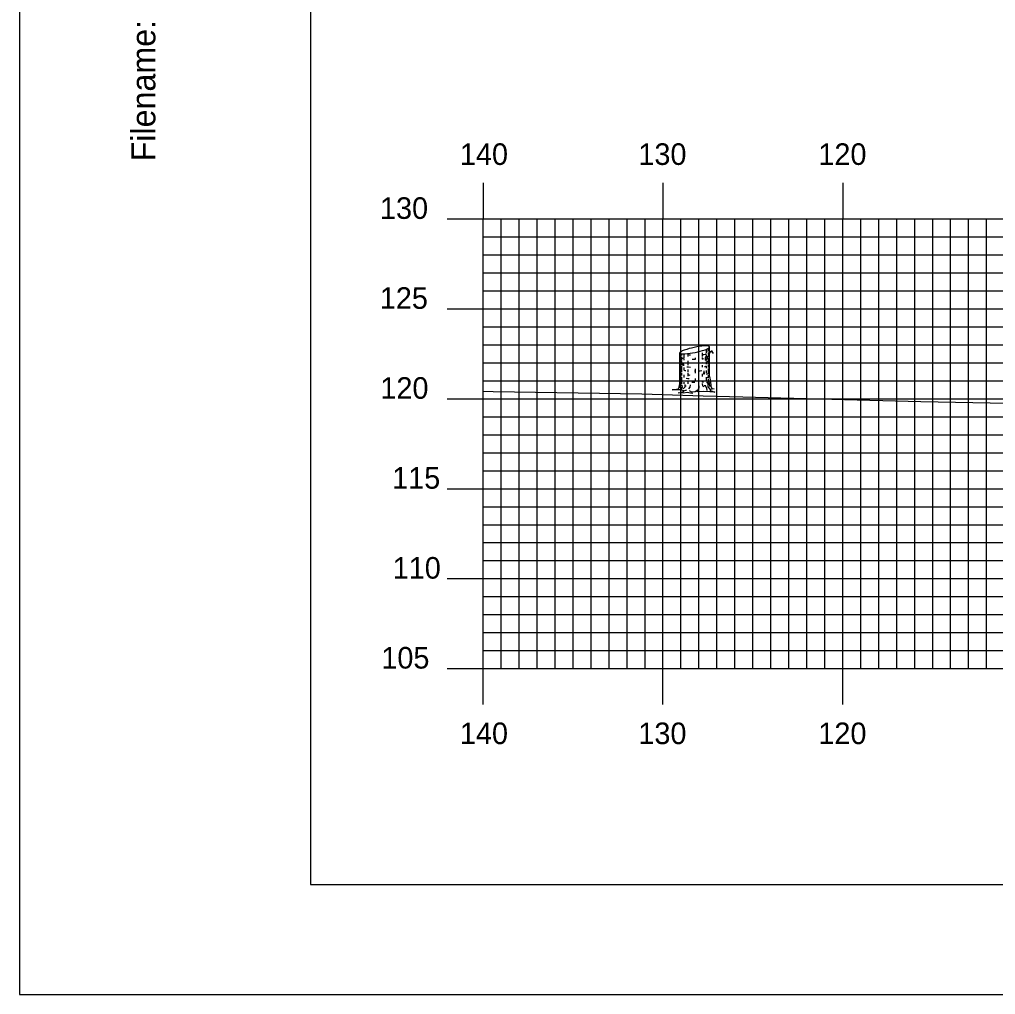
# Model space of a CAD drawing. Extents: x 1772022 to 1772366, y 442591 to 442811.
# Drawn here: x 1772022.3 to 1772076.6, y 442590.5 to 442644.7 of the extents above; entities that cross this region are included whole.
import ezdxf

# ---------------------------------------------------------------- set-up
doc = ezdxf.new("R2010")
doc.units = 0
for name, color, linetype in [('BORDER', 7, 'Continuous'), ('H_V ANNOTATION', 7, 'Continuous'), ('M_Trees_Conifer_Pay', 7, 'Continuous'), ('MAJOR', 7, 'Continuous'), ('MINOR', 7, 'Continuous'), ('PLOT BOUNDARY', 7, 'Continuous'), ('S_Roadway_Centerline', 7, 'Continuous')]:
    doc.layers.add(name, color=color, linetype=linetype)

msp = doc.modelspace()

# ---------------------------------------------------------------- linework, layer by layer
at = {"layer": 'BORDER'}
msp.add_lwpolyline([(1772038.494, 442596.665), (1772358.494, 442596.665), (1772358.494, 442806.665), (1772038.494, 442806.665)], close=True, dxfattribs=at)
at = {"layer": 'M_Trees_Conifer_Pay'}
for p, q in [((1772059.024, 442624.49), (1772059.024, 442626.212)), ((1772059.071, 442626.175), (1772059.071, 442625.704)), ((1772059.129, 442626.164), (1772059.129, 442626.066)), ((1772059.255, 442626.156), (1772059.255, 442625.923)), ((1772059.475, 442626.176), (1772059.475, 442626.008)), ((1772060.27, 442626.218), (1772060.27, 442626.019)), ((1772060.499, 442626.414), (1772060.499, 442626.191)), ((1772060.616, 442626.475), (1772060.616, 442626.313)), ((1772060.616, 442626.245), (1772060.616, 442626.117)), ((1772060.688, 442624.9), (1772060.688, 442626.547)), ((1772059.071, 442625.639), (1772059.071, 442625.331)), ((1772059.129, 442625.992), (1772059.129, 442625.788)), ((1772059.129, 442625.73), (1772059.129, 442625.53)), ((1772059.255, 442625.883), (1772059.255, 442625.809)), ((1772059.475, 442625.771), (1772059.475, 442625.534)), ((1772059.88, 442625.944), (1772059.88, 442625.849)), ((1772060.27, 442625.961), (1772060.27, 442625.872)), ((1772060.499, 442626.103), (1772060.499, 442626.055)), ((1772060.499, 442625.72), (1772060.499, 442625.588)), ((1772060.556, 442625.919), (1772060.505, 442625.86)), ((1772060.616, 442625.93), (1772060.616, 442625.594)), ((1772059.071, 442625.284), (1772059.071, 442624.792)), ((1772059.129, 442625.483), (1772059.129, 442625.147)), ((1772059.129, 442625.094), (1772059.129, 442624.958)), ((1772059.255, 442625.405), (1772059.255, 442625.267)), ((1772059.475, 442625.29), (1772059.475, 442625.137)), ((1772059.475, 442625.094), (1772059.475, 442624.921)), ((1772059.88, 442625.331), (1772059.88, 442625.257)), ((1772059.88, 442625.232), (1772059.88, 442625.084)), ((1772060.27, 442625.524), (1772060.27, 442625.419)), ((1772060.27, 442625.053), (1772060.27, 442624.906)), ((1772060.499, 442625.477), (1772060.499, 442625.368)), ((1772060.499, 442625.232), (1772060.499, 442625.09)), ((1772060.616, 442625.557), (1772060.616, 442625.395)), ((1772060.616, 442625.347), (1772060.616, 442625.131)), ((1772060.616, 442625.1), (1772060.616, 442625.026)), ((1772059.071, 442624.738), (1772059.071, 442624.49)), ((1772059.129, 442624.859), (1772059.129, 442624.481)), ((1772059.255, 442624.995), (1772059.255, 442624.853)), ((1772059.255, 442624.591), (1772059.255, 442624.497)), ((1772059.475, 442624.643), (1772059.475, 442624.49)), ((1772059.88, 442624.792), (1772059.88, 442624.639)), ((1772060.27, 442624.674), (1772060.27, 442624.586)), ((1772060.499, 442624.863), (1772060.499, 442624.69)), ((1772060.616, 442624.985), (1772060.616, 442624.812)), ((1772059.255, 442624.097), (1772059.417, 442624.161)), ((1772059.692, 442624.033), (1772059.566, 442624.097))]:
    msp.add_line(p, q, dxfattribs=at)
for points in [[(1772060.505, 442626.045), (1772060.541, 442625.971), (1772060.589, 442626.028), (1772060.646, 442626.097), (1772060.739, 442626.29), (1772060.803, 442626.337), (1772060.834, 442626.344)], [(1772060.519, 442625.792), (1772060.556, 442625.919), (1772060.62, 442626.035), (1772060.65, 442626.103), (1772060.719, 442626.249)], [(1772060.734, 442626.278), (1772060.809, 442626.286), (1772060.881, 442626.187)], [(1772059.203, 442625.518), (1772059.197, 442625.613), (1772059.24, 442625.59), (1772059.24, 442625.496)], [(1772060.471, 442626.008), (1772060.44, 442625.923), (1772060.436, 442625.856), (1772060.467, 442625.792)], [(1772060.342, 442625.119), (1772060.354, 442625.042), (1772060.402, 442625.053), (1772060.389, 442625.219)], [(1772060.688, 442624.9), (1772060.739, 442624.639), (1772060.755, 442624.365), (1772060.813, 442624.24), (1772060.949, 442624.209), (1772060.719, 442624.171), (1772060.719, 442624.171), (1772060.725, 442624.124), (1772060.972, 442624.03), (1772060.698, 442624.046), (1772060.342, 442624.066), (1772060.02, 442624.056), (1772060.027, 442624.139), (1772059.879, 442624.056), (1772059.692, 442624.033), (1772059.716, 442623.965), (1772059.448, 442624.009), (1772059.228, 442623.982), (1772058.935, 442623.999), (1772059.224, 442624.056), (1772059.255, 442624.097), (1772059.092, 442624.155), (1772058.855, 442624.166), (1772058.614, 442624.166), (1772058.956, 442624.223), (1772058.997, 442624.303), (1772059.024, 442624.49)], [(1772060.278, 442624.507), (1772060.288, 442624.381), (1772060.362, 442624.338)], [(1772060.515, 442624.612), (1772060.589, 442624.507), (1772060.593, 442624.334), (1772060.719, 442624.171)], [(1772060.614, 442624.758), (1772060.62, 442624.612), (1772060.667, 442624.544), (1772060.677, 442624.345)], [(1772059.072, 442624.443), (1772059.051, 442624.365), (1772059.03, 442624.271)], [(1772059.15, 442624.423), (1772059.156, 442624.307), (1772059.102, 442624.219), (1772059.092, 442624.155)], [(1772059.312, 442624.45), (1772059.312, 442624.318), (1772059.224, 442624.219)], [(1772059.539, 442624.209), (1772059.606, 442624.303), (1772059.633, 442624.443)], [(1772060.027, 442624.139), (1772060.101, 442624.28), (1772060.111, 442624.381)], [(1772060.556, 442624.118), (1772060.541, 442624.256), (1772060.467, 442624.385)]]:
    msp.add_lwpolyline(points, dxfattribs=at)
for centre, radius, start, end in [((1772059.055, 442626.211), 0.0314, 156.5158, 169.2194), ((1772059.05, 442626.212), 0.0264, 169.2194, 180.0315), ((1772059.046, 442626.212), 0.0226, 180.0315, 191.7194), ((1772059.046, 442626.212), 0.0226, 191.7194, 203.4074), ((1772059.075, 442626.202), 0.0527, 146.7194, 156.5158), ((1772059.05, 442626.213), 0.0264, 203.4074, 214.2194), ((1772059.054, 442626.216), 0.0314, 214.2194, 226.923), ((1772059.099, 442626.187), 0.0817, 132.3887, 146.7194), ((1772059.069, 442626.232), 0.0527, 226.923, 236.7194), ((1772059.085, 442626.256), 0.0817, 236.7194, 251.0501), ((1772059.213, 442626.062), 0.251, 124.2194, 132.3887), ((1772059.139, 442626.416), 0.251, 251.0501, 259.2194), ((1772059.523, 442625.606), 0.802, 108.0594, 124.2194), ((1772059.242, 442626.957), 0.802, 259.2194, 275.3794), ((1772060.88, 442621.445), 5.179, 101.7194, 108.0594), ((1772058.832, 442631.315), 5.179, 275.3794, 281.7194), ((1772060.88, 442621.445), 5.179, 95.3794, 101.7194), ((1772058.832, 442631.315), 5.179, 281.7194, 288.0594), ((1772059.856, 442630.224), 4.124, 276.238, 278.1032), ((1772060.469, 442625.803), 0.802, 79.2194, 95.3794), ((1772060.357, 442626.707), 0.571, 278.1032, 284.3667), ((1772060.189, 442627.153), 0.802, 288.0594, 304.2194), ((1772060.357, 442626.861), 0.571, 284.4317, 292.4132), ((1772060.357, 442626.707), 0.571, 297.0237, 300), ((1772060.572, 442626.344), 0.251, 71.0501, 79.2194), ((1772060.499, 442626.698), 0.251, 304.2194, 312.3887), ((1772060.556, 442626.516), 0.172, 300, 311.2506), ((1772060.556, 442626.361), 0.172, 300, 311.2506), ((1772060.627, 442626.504), 0.0817, 56.7194, 71.0501), ((1772060.613, 442626.573), 0.0817, 312.3887, 326.7194), ((1772060.628, 442626.433), 0.0624, 311.2506, 330), ((1772060.628, 442626.279), 0.0624, 311.2506, 330), ((1772060.643, 442626.528), 0.0527, 46.923, 56.7194), ((1772060.658, 442626.543), 0.0314, 34.2194, 46.923), ((1772060.637, 442626.557), 0.0527, 326.7194, 336.5158), ((1772060.644, 442626.424), 0.0441, 330, 343.9485), ((1772060.644, 442626.27), 0.0441, 330, 343.9485), ((1772060.662, 442626.546), 0.0264, 23.4074, 34.2194), ((1772060.657, 442626.549), 0.0314, 336.5158, 349.2194), ((1772060.665, 442626.548), 0.0226, 11.7194, 23.4074), ((1772060.665, 442626.548), 0.0226, 0.0315, 11.7194), ((1772060.661, 442626.548), 0.0264, 349.2194, 0.0315), ((1772060.655, 442626.421), 0.0334, 343.9485, 354.2151), ((1772060.655, 442626.267), 0.0334, 343.9485, 354.2151), ((1772059.056, 442626.034), 0.0334, 163.9485, 180), ((1772059.056, 442626.034), 0.0334, 180, 196.0515), ((1772059.056, 442625.587), 0.0334, 163.9485, 180), ((1772059.056, 442625.587), 0.0334, 180, 196.0515), ((1772059.066, 442626.037), 0.0441, 196.0515, 210), ((1772059.066, 442625.59), 0.0441, 196.0515, 210), ((1772059.082, 442626.046), 0.0624, 210, 228.7494), ((1772059.154, 442626.129), 0.172, 228.7494, 240), ((1772059.354, 442626.474), 0.571, 240, 240.3367), ((1772059.355, 442626.263), 0.571, 240, 247.0587), ((1772059.354, 442626.474), 0.571, 246.8597, 257.9846), ((1772059.856, 442630.224), 4.124, 264.6955, 266.7331), ((1772059.855, 442629.991), 4.124, 268.0751, 270), ((1772059.855, 442629.991), 4.124, 270, 270.3581), ((1772059.856, 442629.78), 4.124, 273.7052, 275.9504), ((1772059.855, 442629.991), 4.124, 275.7849, 277.0558), ((1772060.357, 442626.263), 0.571, 284.4493, 297.0429), ((1772060.643, 442625.59), 0.0441, 330, 343.9485), ((1772060.653, 442625.587), 0.0334, 343.9485, 354.2151), ((1772060.654, 442625.823), 0.0334, 343.9485, 354.2151), ((1772059.056, 442625.377), 0.0334, 163.9485, 180), ((1772059.056, 442625.377), 0.0334, 180, 196.0515), ((1772059.056, 442625.14), 0.0334, 163.9485, 180), ((1772059.056, 442625.14), 0.0334, 180, 196.0515), ((1772059.066, 442625.38), 0.0441, 196.0515, 210), ((1772059.066, 442625.143), 0.0441, 196.0515, 210), ((1772059.082, 442625.599), 0.0624, 210, 228.7494), ((1772059.082, 442625.389), 0.0624, 210, 228.7494), ((1772059.082, 442625.152), 0.0624, 210, 228.7494), ((1772059.154, 442625.682), 0.172, 228.7494, 240), ((1772059.154, 442625.472), 0.172, 228.7494, 240), ((1772059.154, 442625.235), 0.172, 228.7494, 240), ((1772059.354, 442626.027), 0.571, 240, 240.3367), ((1772059.354, 442625.817), 0.571, 240, 246.8597), ((1772059.354, 442625.58), 0.571, 240, 246.8597), ((1772059.354, 442625.817), 0.571, 259.2707, 261.8968), ((1772059.855, 442629.334), 4.124, 261.8968, 263.1474), ((1772059.855, 442629.544), 4.124, 264.081, 266.6676), ((1772059.855, 442629.334), 4.124, 270, 270.3581), ((1772059.855, 442629.334), 4.124, 273.1493, 275.4569), ((1772059.855, 442629.544), 4.124, 277.6125, 278.1032), ((1772060.355, 442626.027), 0.571, 278.1032, 286.9296), ((1772060.355, 442625.58), 0.571, 285.3983, 297.1896), ((1772060.355, 442626.027), 0.571, 297.1896, 300), ((1772060.355, 442625.817), 0.571, 297.1896, 300), ((1772060.555, 442625.682), 0.172, 300, 311.2506), ((1772060.555, 442625.472), 0.172, 300, 311.2506), ((1772060.627, 442625.599), 0.0624, 311.2506, 330), ((1772060.627, 442625.389), 0.0624, 311.2506, 330), ((1772060.643, 442625.38), 0.0441, 330, 343.9485), ((1772060.653, 442625.377), 0.0334, 343.9485, 354.2151), ((1772059.056, 442624.943), 0.0334, 163.9485, 180), ((1772059.056, 442624.747), 0.0334, 163.9485, 180), ((1772059.056, 442624.747), 0.0334, 180, 196.0515), ((1772059.056, 442624.527), 0.0334, 163.9485, 180), ((1772059.056, 442624.527), 0.0334, 180, 196.0515), ((1772059.066, 442624.75), 0.0441, 196.0515, 210), ((1772059.066, 442624.53), 0.0441, 196.0515, 210), ((1772059.082, 442624.759), 0.0624, 210, 228.7494), ((1772059.082, 442624.539), 0.0624, 210, 228.7494), ((1772059.154, 442624.842), 0.172, 228.7494, 240), ((1772059.154, 442624.621), 0.172, 228.7494, 240), ((1772059.343, 442625.388), 0.571, 241.2369, 248.0268), ((1772059.354, 442625.187), 0.571, 240, 246.8597), ((1772059.855, 442628.9), 4.124, 263.4991, 265.8397), ((1772059.855, 442629.098), 4.124, 264.716, 266.3193), ((1772059.855, 442628.704), 4.124, 267.8117, 270), ((1772059.855, 442628.704), 4.124, 270, 270.1328), ((1772059.855, 442628.704), 4.124, 275.7849, 276.7896), ((1772060.355, 442625.187), 0.571, 288.5067, 297.2721), ((1772060.355, 442625.382), 0.571, 289.2907, 300), ((1772060.555, 442625.037), 0.172, 300, 311.2506), ((1772060.555, 442624.621), 0.172, 300, 311.2506), ((1772060.627, 442624.955), 0.0624, 311.2506, 330), ((1772060.627, 442624.539), 0.0624, 311.2506, 330), ((1772060.643, 442624.946), 0.0441, 330, 343.9485), ((1772060.643, 442624.53), 0.0441, 330, 343.9485), ((1772060.653, 442624.943), 0.0334, 343.9485, 354.2151), ((1772060.653, 442624.527), 0.0334, 343.9485, 354.2151), ((1772059.354, 442624.966), 0.571, 240, 244.5314), ((1772059.855, 442628.484), 4.124, 262.4438, 263.512), ((1772059.855, 442628.484), 4.124, 277.3684, 278.1032), ((1772060.355, 442624.966), 0.571, 278.1032, 281.637)]:
    msp.add_arc(centre, radius, start, end, dxfattribs=at)
at = {"layer": 'MAJOR'}
for p, q in [((1772048.094, 442635.669), (1772048.094, 442633.665)), ((1772058.094, 442635.669), (1772058.094, 442633.665)), ((1772068.094, 442635.669), (1772068.094, 442633.665)), ((1772046.09, 442633.665), (1772048.094, 442633.665)), ((1772048.094, 442633.665), (1772328.094, 442633.665)), ((1772048.094, 442608.665), (1772048.094, 442633.665)), ((1772048.094, 442608.665), (1772048.094, 442633.665)), ((1772048.094, 442633.665), (1772328.094, 442633.665)), ((1772058.094, 442608.665), (1772058.094, 442633.665)), ((1772068.094, 442608.665), (1772068.094, 442633.665)), ((1772046.09, 442628.665), (1772048.094, 442628.665)), ((1772048.094, 442628.665), (1772328.094, 442628.665)), ((1772046.09, 442623.665), (1772048.094, 442623.665)), ((1772048.094, 442623.665), (1772328.094, 442623.665)), ((1772046.09, 442618.665), (1772048.094, 442618.665)), ((1772048.094, 442618.665), (1772328.094, 442618.665)), ((1772046.09, 442613.665), (1772048.094, 442613.665)), ((1772048.094, 442613.665), (1772328.094, 442613.665)), ((1772046.09, 442608.665), (1772048.094, 442608.665)), ((1772048.094, 442608.665), (1772328.094, 442608.665)), ((1772048.094, 442608.665), (1772328.094, 442608.665)), ((1772048.094, 442606.661), (1772048.094, 442608.665)), ((1772058.094, 442606.661), (1772058.094, 442608.665)), ((1772068.094, 442606.661), (1772068.094, 442608.665))]:
    msp.add_line(p, q, dxfattribs=at)
at = {"layer": 'MINOR'}
for p, q in [((1772049.094, 442608.665), (1772049.094, 442633.665)), ((1772050.094, 442608.665), (1772050.094, 442633.665)), ((1772051.094, 442608.665), (1772051.094, 442633.665)), ((1772052.094, 442608.665), (1772052.094, 442633.665)), ((1772053.094, 442608.665), (1772053.094, 442633.665)), ((1772054.094, 442608.665), (1772054.094, 442633.665)), ((1772055.094, 442608.665), (1772055.094, 442633.665)), ((1772056.094, 442608.665), (1772056.094, 442633.665)), ((1772057.094, 442608.665), (1772057.094, 442633.665)), ((1772059.094, 442608.665), (1772059.094, 442633.665)), ((1772060.094, 442608.665), (1772060.094, 442633.665)), ((1772061.094, 442608.665), (1772061.094, 442633.665)), ((1772062.094, 442608.665), (1772062.094, 442633.665)), ((1772063.094, 442608.665), (1772063.094, 442633.665)), ((1772064.094, 442608.665), (1772064.094, 442633.665)), ((1772065.094, 442608.665), (1772065.094, 442633.665)), ((1772066.094, 442608.665), (1772066.094, 442633.665)), ((1772067.094, 442608.665), (1772067.094, 442633.665)), ((1772069.094, 442608.665), (1772069.094, 442633.665)), ((1772070.094, 442608.665), (1772070.094, 442633.665)), ((1772071.094, 442608.665), (1772071.094, 442633.665)), ((1772072.094, 442608.665), (1772072.094, 442633.665)), ((1772073.094, 442608.665), (1772073.094, 442633.665)), ((1772074.094, 442608.665), (1772074.094, 442633.665)), ((1772075.094, 442608.665), (1772075.094, 442633.665)), ((1772076.094, 442608.665), (1772076.094, 442633.665)), ((1772048.094, 442632.665), (1772328.094, 442632.665)), ((1772048.094, 442632.665), (1772050.098, 442632.665)), ((1772048.094, 442631.665), (1772328.094, 442631.665)), ((1772048.094, 442631.665), (1772050.098, 442631.665)), ((1772048.094, 442630.665), (1772328.094, 442630.665)), ((1772048.094, 442630.665), (1772050.098, 442630.665)), ((1772048.094, 442629.665), (1772328.094, 442629.665)), ((1772048.094, 442629.665), (1772050.098, 442629.665)), ((1772048.094, 442627.665), (1772328.094, 442627.665)), ((1772048.094, 442627.665), (1772050.098, 442627.665)), ((1772048.094, 442626.665), (1772328.094, 442626.665)), ((1772048.094, 442626.665), (1772050.098, 442626.665)), ((1772048.094, 442625.665), (1772328.094, 442625.665)), ((1772048.094, 442625.665), (1772050.098, 442625.665)), ((1772048.094, 442624.665), (1772328.094, 442624.665)), ((1772048.094, 442624.665), (1772050.098, 442624.665)), ((1772048.094, 442622.665), (1772328.094, 442622.665)), ((1772048.094, 442622.665), (1772050.098, 442622.665)), ((1772048.094, 442621.665), (1772328.094, 442621.665)), ((1772048.094, 442621.665), (1772050.098, 442621.665)), ((1772048.094, 442620.665), (1772328.094, 442620.665)), ((1772048.094, 442620.665), (1772050.098, 442620.665)), ((1772048.094, 442619.665), (1772328.094, 442619.665)), ((1772048.094, 442619.665), (1772050.098, 442619.665)), ((1772048.094, 442617.665), (1772328.094, 442617.665)), ((1772048.094, 442617.665), (1772050.098, 442617.665)), ((1772048.094, 442616.665), (1772328.094, 442616.665)), ((1772048.094, 442616.665), (1772050.098, 442616.665)), ((1772048.094, 442615.665), (1772328.094, 442615.665)), ((1772048.094, 442615.665), (1772050.098, 442615.665)), ((1772048.094, 442614.665), (1772328.094, 442614.665)), ((1772048.094, 442614.665), (1772050.098, 442614.665)), ((1772048.094, 442612.665), (1772328.094, 442612.665)), ((1772048.094, 442612.665), (1772050.098, 442612.665)), ((1772048.094, 442611.665), (1772328.094, 442611.665)), ((1772048.094, 442611.665), (1772050.098, 442611.665)), ((1772048.094, 442610.665), (1772328.094, 442610.665)), ((1772048.094, 442610.665), (1772050.098, 442610.665)), ((1772048.094, 442609.665), (1772328.094, 442609.665)), ((1772048.094, 442609.665), (1772050.098, 442609.665))]:
    msp.add_line(p, q, dxfattribs=at)
at = {"layer": 'PLOT BOUNDARY'}
msp.add_lwpolyline([(1772022.307, 442590.547), (1772362.307, 442590.547), (1772362.307, 442810.547), (1772022.307, 442810.547)], close=True, dxfattribs=at)
at = {"layer": 'S_Roadway_Centerline'}
msp.add_lwpolyline([(1772048.094, 442624.091), (1772048.645, 442624.074), (1772056.917, 442623.94), (1772060.336, 442623.826), (1772062.537, 442623.767), (1772072.431, 442623.514), (1772083.062, 442623.311), (1772084.029, 442623.273), (1772085.156, 442623.259), (1772103.826, 442623.123), (1772107.742, 442623.013), (1772113.071, 442622.879), (1772118.469, 442622.625), (1772122.768, 442622.336), (1772139.063, 442622.291)], dxfattribs=at)

# ---------------------------------------------------------------- texts
at = {"layer": 'BORDER'}
msp.add_text('Filename:', height=1.3392, rotation=90, dxfattribs=at).set_placement((1772029.863, 442636.862))
at = {"layer": 'H_V ANNOTATION'}
for s, p in [('140', (1772046.798, 442636.665)), ('130', (1772056.723, 442636.665)), ('120', (1772066.734, 442636.665)), ('130', (1772042.353, 442633.665)), ('125', (1772042.343, 442628.665)), ('120', (1772042.375, 442623.665)), ('115', (1772043.028, 442618.665)), ('110', (1772043.06, 442613.665)), ('105', (1772042.428, 442608.665)), ('140', (1772046.798, 442604.465)), ('130', (1772056.723, 442604.465)), ('120', (1772066.734, 442604.465))]:
    msp.add_text(s, height=1.2, dxfattribs=at).set_placement(p)
at = {"layer": 'MAJOR'}
msp.add_text('-', height=0.012, dxfattribs=at).set_placement((1772048.085, 442608.665))

doc.saveas('drawing.dxf')
